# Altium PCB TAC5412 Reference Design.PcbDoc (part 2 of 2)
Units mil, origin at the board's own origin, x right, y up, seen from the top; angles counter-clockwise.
Board outline 3000 x 3000 mil, 6 copper layers (Top Layer, GND 1, Signal, GND 2, PWR, Bottom Layer), stack 60.4 mil thick; 137 components, 64 nets, 376 pads, 151 vias.
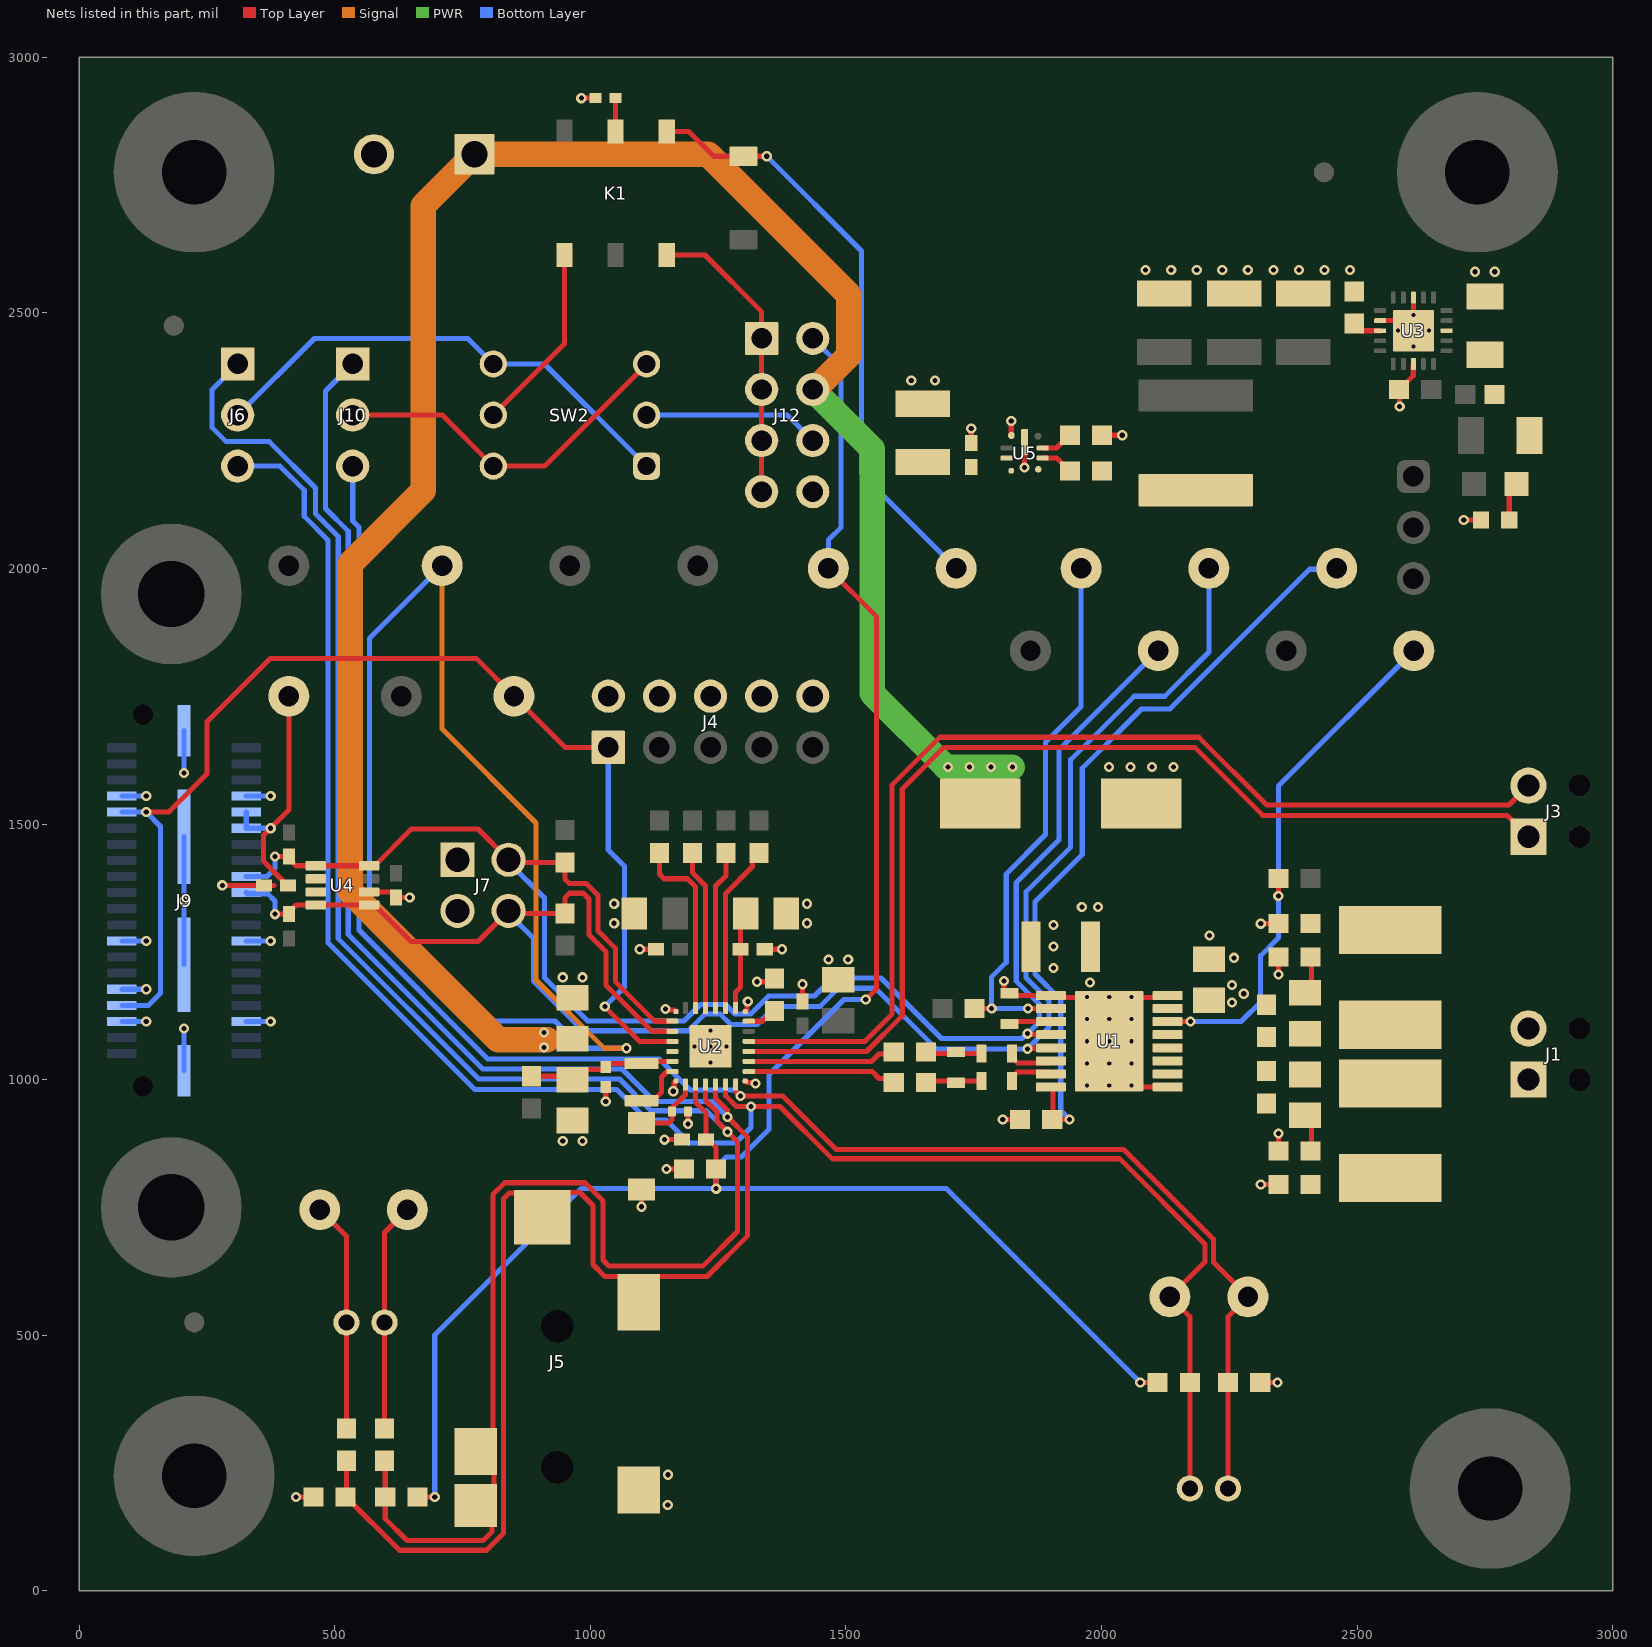
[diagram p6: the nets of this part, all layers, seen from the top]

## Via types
v1: diameter 20, hole 10, Top Layer to Bottom Layer, tented both sides, 127 vias
v2: diameter 19.68, hole 7.87, Top Layer to Bottom Layer, 19 vias
v3: diameter 19.68, hole 7.87, Top Layer to Bottom Layer, tented both sides, 5 vias

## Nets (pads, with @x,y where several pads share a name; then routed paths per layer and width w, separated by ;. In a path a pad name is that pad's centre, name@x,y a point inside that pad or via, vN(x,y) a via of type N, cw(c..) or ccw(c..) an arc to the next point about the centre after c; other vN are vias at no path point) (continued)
GND: C1.2 C2.1 C3.2 C4.2 C5.2 C11.1 C12.1 C13.2 C14.2 C15.2 C16.2 C17.2 C18.2 C19.2 C20.2 C21.2 C22.2 C23.1 C24.1 C25.2 C26.2 C27.2 C31.2 C32.2 C33.1 C34.1 C36.2 C37.2 C38.2 C39.2 C40.2 C41.2 J2.2 J4.2 J4.4 J4.6 J4.8 J4.10 J5.1 J7.1 J7.3 J9.7 J9.8 J9.25 J9.26 J9.31 J9.35 J9.36 J9.41 J9.42 J9.43 J9.44 J12.8 R5.1 R13.2 R17.2 R21.2 R22.1 R26.1 U1.1 U1.9 U1.16 U1.17 U2.25 U2.A1 U2.A2 U2.A3 U2.A4 U3.8 U3.12 U3.18 U3.21 U4.6 U5.1 U5.9 | length 2548.7
  Top Layer w10: v1(280,1380) 381.38,1380 ; v1(424.22,183.62) R13.2@458.1,183.62 ; U4.6@567.25,1367.21 609.17,1367.21 609.25,1367.13 613.19,1367.13 620,1360.32 C34.1@620,1356.38 v1(646.38,1356.38) ; v1(982.22,2919.9) R26.1@1009.99,2919.9 ; v1(1030,957.32) C17.2@1030,985.32 C17.2@1030,991.2 ; v1(1096.47,1255) C20.2@1130.35,1255 ; v1(1100,751.16) C23.1@1100,785.04 ; v1(1145,882.5) C25.2@1178.88,882.5 ; v1(1147.09,1137.91) 1149,1136 1164,1136 U2.A2@1167.09,1132.91 ; v1(1149.11,825) C26.2@1182.99,825 ; v1(1162.09,977.09) 1164,979 1164,994 U2.A3@1167.09,997.09 ; v1(1190.75,913.46) C24.1@1190.75,937.5 ; U2.A4@1302.91,997.09 1306,994 1321,994 v1(1322.91,992.09) ; U2.A1@1302.91,1132.91 1306,1136 1306,1151 v1(1307.91,1152.91) ; v1(1326.12,1191.5) C27.2@1360,1191.5 ; C22.2@1341.12,1255 v1(1375,1255) ; C14.2@1415,1152.62 v1(1415,1186.5) ; C37.2@1745,2245.52 v1(1745,2273.69) ; v1(1806.63,922) R5.1@1840.51,922 ; v1(1809.02,1192.8) 1809.02,1173.98 1814.02,1168.98 C15.2@1820,1168.98 1824.41,1164.57 U1.1@1900.83,1164.57 1904.69,1160.71 1971.54,1160.71 1971.69,1160.55 v2(1971.69,1118.31) ; U5.1@1823.33,2260.03 v1(1823.33,2288.21) ; v1(1849.37,2197.33) U5.9@1849.37,2225.51 ; U1.17@1975.78,1122.39 U1.17@2015,1083.17 ; C41.2@2000.87,2260.51 v1(2040.4,2260.51) ; v2(2015,988.39) 2017.95,985.43 U1.9@2129.17,985.43 ; v2(2015,1075) U1.17@2015,1083.17 ; U1.17@2054.22,1122.39 U1.17@2015,1083.17 ; v2(2058.31,1118.31) 2058.31,1160.71 2125.32,1160.71 U1.16@2129.17,1164.57 ; R17.2@2310.39,407.5 v1(2344.27,407.5) ; v1(2311.28,795) C12.1@2345.78,795 ; v1(2311.28,1305) C4.2@2345.78,1305 ; C11.1@2346.27,860.02 v1(2346.27,894.52) ; v1(2346.27,1205.5) C5.2@2346.27,1240 ; U3.12@2545.04,2484.69 2590.32,2484.69 2605.08,2469.92 2610,2474.84 v2(2610,2495.51) U3.8@2610,2529.96 ; v1(2583.08,2316.89) 2583.08,2348.99 C31.2@2582.01,2350.07 2582.99,2350.07 2609.72,2376.8 2609.72,2399.76 U3.18@2610,2400.04 ; v1(2708.44,2094.64) 2742.08,2094.64 R21.2@2742.44,2095
  Bottom Layer w10: J9.35@83.35,1113.78 v1(131.14,1113.78) ; J9.31@83.35,1176.77 v1(131.14,1176.77) ; J9.25@83.35,1271.26 v1(131.14,1271.26) ; J9.7@83.35,1554.72 v1(131.14,1554.72) ; J9.44@205,1017.52 v1(205,1100.1) ; J9.43@205,1225 v1(205,1349.9) J9.42@205,1475 ; v1(205,1599.9) J9.41@205,1682.48 ; J9.36@326.65,1113.78 v1(374.45,1113.78) ; J9.26@326.65,1271.26 v1(374.45,1271.26) ; J9.8@326.65,1554.72 v1(374.45,1554.72)
  other v1: 1151.34,167.94 1151.59,227.06 945.98,879.94 984.26,879.94 1977.09,1190 945.98,1200.06 984.26,1200.06 1465.98,1235.06 1504.26,1235.06 2259.04,1238.19 2211.03,1282.02 1046.44,1305.74 1423.56,1305.74 1961.34,1337.89 1992.83,1337.89 1046.44,1344.02 1423.56,1344.02 2014.44,1611.32 2056.47,1611.32 2098.49,1611.32 2140.52,1611.32 1627.63,2367.61 1674.28,2367.61 2730.74,2580.26 2769.02,2580.26 2086.11,2583.52 2136.11,2583.52 2186.11,2583.52 2236.11,2583.52 2286.11,2583.52 2336.11,2583.52 2386.11,2583.52 2436.11,2583.52 2486.11,2583.52
  other v2: 1971.69,988.39 2058.31,988.39 1971.69,1031.69 2015,1031.69 2058.31,1031.69 1971.69,1075 2058.31,1075 2015,1118.31 1971.69,1161.61 2015,1161.61 2058.31,1161.61 2610,2434.49 2579.49,2465 2640.51,2465
  other v3: 1235,1033.5 1203.5,1065 1235,1065 1266.5,1065 1235,1096.5
IN1M_D: J5.3 J5.5 J10.1 R13.1 R16.2 U2.16 | length 4192
  Top Layer w10: R13.1@522.07,183.62 626.41,79.28 796.81,79.28 830.2,112.68 830.2,767.13 841.36,778.28 858.22,778.28 J5.5@906,730.5 954.5,779 979.87,779 1005,753.87 1005,638.26 1028.26,615 1058,615 J5.3@1094.5,578.5 ; R13.1@522.6,185.13 R16.2@522.6,254.44 ; J5.3@1094.5,564.5 J5.3@1094.5,578.5 ; U2.16@1244.84,990.2 1244.84,963.39 1268.29,939.94 v1(1268.29,926.67) 1307.6,887.36 1307.6,694.35 1228.24,615 1131,615 J5.3@1094.5,578.5
  Bottom Layer w10: J10.1@535,2400 481.88,2346.89 481.88,2117.18 526.21,2072.85 526.21,1283.77 789.47,1020.51 1061.82,1020.51 1125.24,957.09 1237.87,957.09 v1(1268.29,926.67)
IN1P_D: J5.2 J5.4 J6.1 R12.1 R15.2 U2.15 | length 4244.4
  Top Layer w10: R15.2@597.4,254.44 598.69,253.16 R12.1@598.69,183.55 598.69,140.86 641.36,98.19 790.25,98.19 807.42,115.36 807.42,134.58 J5.4@775.5,166.5 811.66,202.66 811.66,236.34 J5.2@775.5,272.5 809.56,306.56 809.56,775.54 832.28,798.27 989.5,798.27 1024.69,763.07 1024.69,646.91 1036.61,635 1219.96,635 1287.6,702.64 1287.6,878.48 v1(1268.29,897.79) 1248,918.07 1248,936.5 1225.16,959.34 U2.15@1225.16,990.2
  Bottom Layer w10: J6.1@310,2400 260,2350 260,2275.33 287.43,2247.9 371.72,2247.9 462.1,2157.52 462.1,2107.04 506.69,2062.45 506.69,1275.68 781.43,1000.94 1056.73,1000.94 1118.62,939.04 1227.04,939.04 v1(1268.29,897.79)
IN2M_D: J10.3 MIC2M.1 MK2.2 R17.1 U2.18 | length 3392.8
  Top Layer w10: U2.18@1284.21,990.2 1284.21,977.27 v1(1293.59,967.89) 1376.11,967.89 1480.38,863.62 2042.94,863.62 2218.72,687.84 2218.72,642.66 MIC2M.1@2286.38,575 2247.4,536.02 R17.1@2247.4,407.5 MK2.2@2247.4,200
  Bottom Layer w10: J10.3@535,2200 535,2092.62 547.12,2080.5 547.12,1292.42 799.02,1040.51 1134.78,1040.51 1195.45,979.84 1281.64,979.84 v1(1293.59,967.89)
IN2P_D: J6.3 MIC2P.1 MK2.1 R14.2 U2.17 | length 3699.9
  Top Layer w10: U2.17@1264.53,983.39 U2.17@1264.53,990.2 ; U2.17@1264.61,983.39 1264.61,968.19 1285.33,947.46 v1(1314.02,947.46) 1370.96,947.46 1473.23,845.19 2035.31,845.19 2201.93,678.57 2201.93,643.31 MIC2P.1@2133.62,575 2172.6,536.02 R14.2@2172.6,407.5 MK2.1@2172.6,200
  Bottom Layer w10: J6.3@310,2200 392.97,2200 440.15,2152.82 440.15,2101.89 486.91,2055.13 486.91,1267.49 773.74,980.66 1051.37,980.66 1111.16,920.87 1148.13,920.87 1193.08,875.92 1283.87,875.92 1314.02,906.07 v1(1314.02,947.46)
INM-A: J10.2 SW2.3 SW2.6 | length 674.3
  Top Layer w10: J10.2@560,2300 710,2300 SW2.6@810,2200 910,2200 SW2.3@1110,2400
INP-A: J6.2 SW2.1 SW2.4 | length 965.7
  Bottom Layer w10: J6.2@310,2300 460,2450 760,2450 SW2.4@810,2400 910,2400 SW2.1@1110,2200
IOVDD-MB: C33.2 IOVDD-MB1.1 J9.10 J9.12 U4.2 U4.3 | length 492
  Top Layer w10: C33.2@408.62,1380 404.68,1380 397.87,1386.81 397.87,1389.72 360.55,1427.04 360.55,1477.83 410,1527.28 IOVDD-MB1.1@410,1750
  Bottom Layer w10: J9.10@326.65,1523.23 J9.12@326.65,1491.73 v1(374.45,1491.73)
IRQ/IRQZ: J4.1 J9.9 J9.33 MCLK.1 U2.9 | length 2355.7
  Top Layer w10: v1(131.14,1523.23) 175.11,1523.23 250,1598.12 250,1660 250.11,1660.11 250.11,1699.92 374.22,1824.03 776.47,1824.03 MCLK.1@850.5,1750 950.5,1650 J4.1@1035,1650 ; v1(1028.26,1142.8) 1028.26,1142.55 1095.96,1074.84 U2.9@1160.2,1074.84
  Bottom Layer w10: J9.33@83.35,1145.28 135.39,1145.28 159.13,1169.02 159.13,1495.24 v1(131.14,1523.23) J9.9@83.35,1523.23 ; v1(1028.26,1142.8) 1066.53,1181.07 1066.53,1417.51 1035,1449.04 J4.1@1035,1650
MICBIAS: C25.1 C26.1 J12.2 MICBIAS1.1 R12.2 R14.1 U2.14 | length 4171
  Top Layer w10: R12.2@661.68,183.55 v1(695.56,183.55) ; U2.14@1205.47,990.2 1205.47,955.68 1226.12,935.03 C25.1@1226.12,882.5 1230.06,882.5 1245.98,866.58 C26.1@1245.98,825 v1(1245.98,786.61) ; MICBIAS1.1@1465.5,2000 1560,1905.5 1560,1177.8 v1(1538.69,1156.5) ; v1(2075.73,407.5) R14.1@2109.61,407.5
  Bottom Layer w10: v1(695.56,183.55) 695.56,500.56 981.61,786.61 v1(1245.98,786.61) ; J12.2@1435,2450 1490.5,2394.5 1490.5,2080.5 1465.5,2055.5 MICBIAS1.1@1465.5,2000 ; v1(1538.69,1156.5) 1496.12,1156.5 1349.49,1009.87 1349.49,902.96 1295.37,848.84 1266.39,848.84 1245.98,828.42 v1(1245.98,786.61) ; v1(2075.73,407.5) 1696.62,786.61 v1(1245.98,786.61)
NetC4_1: C4.1 J1.2 L1.2
NetC5_1: C5.1 R1.1 | length 78.8
  Top Layer w10: R1.1@2397.75,1170 2410.55,1182.8 C5.1@2410.55,1243.5
NetC6_1: C6.1 U1.6 | length 89.4
  Top Layer w10: C6.1@1825,1051 1825,1043.5 1835.74,1032.76 1896.97,1032.76 U1.6@1900.83,1036.61
NetC6_2: C6.2 C10.2 R6.2 | length 119.7
  Top Layer w10: R6.2@1646.5,1054 1649.5,1051 C6.2@1765,1051
NetC7_1: C7.1 L1.1 R1.2 U1.12
NetC7_2: C7.2 U1.13
NetC8_1: C8.1 U1.7 | length 89.4
  Top Layer w10: C8.1@1825,996.64 1825,1004.14 1835.74,1014.88 1896.97,1014.88 U1.7@1900.83,1011.02
NetC8_2: C8.2 C10.1 R7.2 | length 119.7
  Top Layer w10: R7.2@1646.5,994 1649.5,997 C8.2@1765,997
NetC9_1: C9.1 L2.1 R4.1 U1.11
NetC9_2: C9.2 U1.10
NetC11_2: C11.2 R4.2 | length 78.8
  Top Layer w10: R4.2@2397.75,930 2410.55,917.2 C11.2@2410.55,856.5
NetC12_2: C12.2 J1.1 L2.2
NetC15_1: C15.1 U1.3 | length 82.7
  Top Layer w10: C15.1@1820,1108.98 1824.41,1113.39 U1.3@1900.83,1113.39
NetC17_1: C17.1 C18.1 L3.1 L4.1 U2.11 | length 293.7
  Top Layer w10: L3.1@885,1006.5 958.5,1006.5 C18.1@965,1000 985,1020 1025.32,1020 C17.1@1030,1024.69 1030,1026.58 1034.84,1031.42 L4.1@1100,1031.42 1103.98,1035.39 1160.12,1035.39 U2.11@1160.2,1035.47
NetC21_1: C21.1 C22.1 U2.1 | length 193.2
  Top Layer w10: U2.1@1284.21,1139.8 1284.21,1171.48 1293.88,1181.14 1293.88,1315.38 C21.1@1303.5,1325
NetC23_2: C23.2 C24.2 U2.13 | length 142
  Top Layer w10: C23.2@1100,914.96 1153.39,914.96 1159.25,920.82 C24.2@1159.25,937.5 1162.13,940.37 1162.13,947.1 1185.79,970.76 U2.13@1185.79,990.2
NetC27_1: C27.1 U2.24 | length 60.8
  Top Layer w10: U2.24@1309.8,1114.21 1336.69,1114.21 1360,1137.52 C27.1@1360,1138.5
NetC30_1: C30.1 R20.1 R22.2 U3.3
NetC32_1: C32.1 U3.13 | length 56.7
  Top Layer w10: C32.1@2494.37,2479.02 2494.37,2478.7 2508.07,2465 U3.13@2545.04,2465
NetC35_1: C35.1 U5.6 | length 64.1
  Top Layer w10: U5.6@1884.8,2215.67 1912.72,2215.67 1923.19,2205.2 1923.19,2204.21 1936.89,2190.51 C35.1@1937.87,2190.51
NetC35_2: C35.2 L5.1 U5.5
NetC41_1: C41.1 U5.7 | length 63.5
  Top Layer w10: U5.7@1884.8,2235.35 1911.73,2235.35 1936.89,2260.51 C41.1@1937.87,2260.51
NetD1_2: D1.2 R21.1 | length 75.7
  Top Layer w10: R21.1@2797.56,2095 2797.56,2151.22 D1.2@2811.34,2165
NetDIAGSW1_1: DIAGSW1.1 K1.1 SW1.2 | length 1175.6
  Top Layer w10: K1.1@1149.36,2854.98 1191.92,2854.98 1240.63,2806.28 SW1.2@1299.36,2806.28 v1(1345,2806.28)
  Bottom Layer w10: v1(1345,2806.28) 1530.15,2621.12 1530.15,2185.35 DIAGSW1.1@1715.5,2000
NetFAULT_1: FAULT.1 R2.2 U1.14 | length 1044
  Top Layer w10: U1.14@2129.17,1113.39 v1(2174,1113.39) ; v1(2345.78,1359.18) R2.2@2345.78,1393.68
  Bottom Layer w10: v1(2174,1113.39) 2272.65,1113.39 2311.24,1151.97 2311.24,1242.33 2345.78,1276.88 v1(2345.78,1359.18) 2345.78,1574.23 FAULT.1@2610.9,1839.35
NetJ3_1: J3.1 U2.21 | length 2104
  Top Layer w10: U2.21@1309.8,1055.16 1540.28,1055.16 1609.94,1124.82 1609.94,1568.46 1691.48,1650 2182.11,1650 2315.11,1517 2793,1517 J3.1@2835,1475
NetJ3_2: J3.2 U2.22 | length 2105
  Top Layer w10: U2.22@1309.8,1074.84 1536.92,1074.84 1590.26,1128.18 1590.26,1576.61 1683.33,1669.69 2190.26,1669.69 2322.95,1537 2797,1537 J3.2@2835,1575
NetJ12_1: J12.1 J12.3 J12.5 J12.7 K1.6 | length 583.5
  Top Layer w10: K1.6@1149.36,2612.86 1224.02,2612.86 1335,2501.87 J12.7@1335,2150
NetJ12_6: J12.6 SW2.2 | length 345.7
  Bottom Layer w10: SW2.2@1110,2300 1385,2300 J12.6@1435,2250
NetK1_2: K1.2 R26.2 | length 64.9
  Top Layer w10: K1.2@1049.36,2854.98 R26.2@1049.36,2919.9
NetK1_4: K1.4 SW2.5 | length 370.6
  Top Layer w10: SW2.5@810,2300 949.36,2439.36 K1.4@949.36,2612.86
NetL4_2: L4.2 U2.12 | length 101.3
  Top Layer w10: L4.2@1100,958.58 1122.64,958.58 1139.11,975.05 1139.11,1004.85 1150.05,1015.79 U2.12@1160.2,1015.79
NetMIC1M_1: MIC1M.1 MK1.2 R16.1 | length 449.5
  Top Layer w10: MIC1M.1@470.61,745.48 522.6,693.49 MK1.2@522.6,525 R16.1@522.6,317.5
NetMIC1P_1: MIC1P.1 MK1.1 R15.1 | length 446.5
  Top Layer w10: R15.1@597.4,317.43 MK1.1@597.4,525 597.4,700.88 MIC1P.1@641.99,745.48
NetMUTE_1: MUTE.1 R5.2 U1.8 | length 1512.5
  Top Layer w10: U1.8@1900.83,985.43 1901.14,985.43 1905,981.58 R5.2@1905,922 ; R5.2@1903.5,922 R5.2@1905,922 ; v1(1937.38,922) R5.2@1905,922
  Bottom Layer w10: v1(1937.38,922) 1920.05,939.34 1920.05,1156.4 1869.67,1206.77 1869.67,1348.12 1962.13,1440.57 1962.13,1609.12 2078.01,1725 2133.56,1725 2406.83,1998.27 2449.11,1998.27 2450.84,2000 MUTE.1@2460,2000
NetR3_2: R3.2 STANDBY.1 U1.2 | length 1082.8
  Top Layer w10: R3.2@1751.5,1138.98 v1(1785,1138.98) ; v1(1856,1138.98) U1.2@1900.83,1138.98
  Bottom Layer w10: v1(1856,1138.98) v1(1785,1138.98) 1785,1200.97 1813.42,1229.39 1813.42,1402.32 1890.35,1479.26 1890.35,1660.06 1960,1729.72 STANDBY.1@1960,2000
NetR6_1: R6.1 U2.20 | length 281.4
  Top Layer w10: U2.20@1309.8,1035.47 1549.85,1035.47 1564.68,1050.3 1579.8,1050.3 R6.1@1583.5,1054
NetR7_1: R7.1 U2.19 | length 284.9
  Top Layer w10: U2.19@1309.8,1015.79 1551.24,1015.79 1564.68,1002.35 1578.82,1002.35 1583.5,997.67 R7.1@1583.5,994
NetR8_1: R8.1 U2.2 | length 330.8
  Top Layer w10: U2.2@1264.53,1139.8 1264.53,1363.98 1317.23,1416.68 1317.23,1430.73 R8.1@1330,1443.5
NetR9_1: R9.1 U2.5 | length 361.8
  Top Layer w10: R9.1@1135,1443.5 1135,1401.98 1144.19,1392.8 1189.7,1392.8 1205.47,1377.02 U2.5@1205.47,1139.8 ; R9.1@1135,1446.69 R9.1@1136.59,1445.1
NetR10_1: R10.1 U2.4 | length 314.1
  Top Layer w10: R10.1@1200,1443.5 1200,1403.99 1225.16,1378.84 U2.4@1225.16,1139.8
NetR11_1: R11.1 U2.3 | length 312.1
  Top Layer w10: U2.3@1244.84,1139.8 1244.84,1378.48 1265,1398.64 R11.1@1265,1443.5
SCL: J7.2 J9.18 R18.2 R23.1 SCL1.1 U1.4 U2.7 U4.1 U4.8 | length 3407.7
  Top Layer w10: v1(383.19,1436.38) R23.1@410,1436.38 410,1432.44 424.06,1418.39 U4.1@462.75,1418.39 U4.8@567.25,1418.39 578,1418.39 649.65,1490.04 779.96,1490.04 J7.2@840,1430 ; J7.2@865,1425 R18.2@950,1425 950,1392.39 958.5,1383.88 991.59,1383.88 1015.11,1360.35 1015.11,1290.64 1048.75,1257 1048.75,1191.56 1126.1,1114.21 U2.7@1160.2,1114.21 ; v1(1855,1089.8) 1856,1088.8 1899.83,1088.8 U1.4@1900.83,1087.8
  Bottom Layer w10: J9.18@326.65,1397.24 326.94,1397.53 367.14,1397.53 383.19,1413.58 v1(383.19,1436.38) ; J7.2@840,1425 910,1355 910,1199.29 994.9,1114.39 1183.18,1114.39 1215.58,1146.79 1264.2,1146.79 1283,1127.99 1313.31,1127.99 1348.81,1163.49 1438.49,1163.49 1473.99,1198.99 1568.27,1198.99 1686.97,1080.29 1844.14,1080.29 1853.65,1089.8 v1(1855,1089.8) 1878.38,1113.17 1878.38,1147.32 1833.14,1192.55 1833.14,1385.43 1916.83,1469.12 1916.83,1645.28 SCL1.1@2110.9,1839.35
SDA: J7.4 J9.20 R19.2 R24.1 SDA1.1 U1.5 U2.8 U4.4 U4.5 | length 3595.7
  Top Layer w10: v1(383.19,1323.62) R24.1@410,1323.62 410,1327.56 424.06,1341.62 U4.4@462.75,1341.62 U4.5@567.25,1341.62 578,1341.62 649.65,1269.96 779.96,1269.96 J7.4@840,1330 ; J7.4@865,1325 R19.2@950,1325 950,1355.18 959.28,1364.46 986.23,1364.46 997.24,1353.46 997.24,1283.23 1030.88,1249.6 1030.88,1184.16 1120.51,1094.53 U2.8@1160.2,1094.53 ; v1(1855,1060.21) 1856,1061.21 1899.83,1061.21 U1.5@1900.83,1062.21
  Bottom Layer w10: J9.20@326.65,1365.75 328.76,1363.65 368.86,1363.65 383.19,1349.32 v1(383.19,1323.62) ; J7.4@840,1325 888.46,1276.54 888.46,1192.8 985.62,1095.64 1191.43,1095.64 1223.78,1127.99 1254.22,1127.99 1274.42,1107.79 1326.42,1107.79 1361.9,1143.27 1449.58,1143.27 1485.06,1178.75 1557.86,1178.75 1676.4,1060.21 v1(1855,1060.21) 1897.46,1102.66 1897.46,1153.97 1852.46,1198.96 1852.46,1367.45 1939.45,1454.44 1939.45,1625.6 2063.85,1750 2123.49,1750 2210,1836.51 SDA1.1@2210,2000
VBATIN: C1.1 C2.2 C3.1 C16.1 C36.1 C37.1 J2.1 J12.4 U1.15 U2.10 U5.3 U5.4 VBAT.1 | length 6572.8
  PWR w50: J12.4@1435,2350 1551.12,2233.88 1551.12,1755.6 1695.4,1611.32 v1(1699.48,1611.32) v1(1741.51,1611.32) v1(1783.53,1611.32) v1(1825.56,1611.32)
  Signal w10: VBAT.1@710,2005.5 710,1685.93 893.8,1502.13 893.8,1194.62 1027,1061.42 v1(1070.75,1061.42)
  Signal w50: 915.22,1078.09 819.59,1078.09 530.31,1367.37 530.31,2009.28 672.74,2151.71 672.74,2709.48 J2.1@773.43,2810.16 1230.52,2810.16 1505.5,2535.18 1505.5,2416.45 1439.05,2350 J12.4@1435,2350
  Bottom Layer w10: VBAT.1@710,2005.5 567.48,1862.98 567.48,1301.02 754.08,1114.42 930.58,1114.42 983.58,1061.42 v1(1070.75,1061.42)
  other v1: 909.19,1063.15 909.19,1092.09 2255,1150.91 2278.16,1167.96 2255,1185 1905.92,1218.23 1905.92,1260.25 1905.92,1302.28
pads on no net: FID1.1 FID2.1 FID3.1 FID4.1 FID5.1 FID6.1 H1.1 H2.1 H3.1 H4.1 H5.0 H6.0 H7.0 H8.0 H9.0 H10.0 H11.0 H12.0 J1.MH1 J1.MH2 J3.MH1 J3.MH2 J5.MH1 J5.MH2 J9.1 J9.2 J9.3 J9.4 J9.5 J9.6 J9.11 J9.13 J9.14 J9.15 J9.16 J9.17 J9.19 J9.21 J9.22 J9.23 J9.24 J9.28 J9.29 J9.30 J9.38 J9.40 J9.45 J9.46 K1.3 K1.5 U3.2 U3.4 U3.5 U3.6 U3.7 U3.9 U3.10 U3.11 U5.2

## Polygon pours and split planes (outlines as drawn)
GND on PWR "GND" (solid, remove dead copper, pour order 4): 3000,3000 0,3000 0,0 3000,0
"+3.3V MB" on PWR "+3.3V MB" (solid, remove dead copper, pour order 0): 588.15,1500 429.47,1500 424.42,1494.95 424.42,1041.91 760.86,705.48 2169.79,705.48 2749.38,1285.07 2749.38,1609.96 2864.9,1725.47 2864.9,1884.3 2725.59,2023.6 2584.22,2023.6 2573.11,2012.49 2573.11,1921.31 2584.24,1910 2654.26,1910 2700.9,1863.36 2700.9,1818.64 2562.91,1680.65 2562.91,1352.3 2108.4,897.79 853.33,897.79 672.15,1078.97 672.15,1416
+3.3V on PWR "+3.3V Analog" (solid, remove dead copper, pour order 3): 891.42,907.98 862.04,907.98 830.5,939.53 830.5,1085.94 864.23,1119.67 1200.5,1119.67 1623.95,1543.12 1868.25,1543.12 1900.9,1575.77 1900.9,2090.57 1491.47,2500 1264.73,2500 1218.3,2546.43 1218.3,2643.57 1249.73,2675 1981.42,2675 2366.4,2290.02 2653.63,2290.02 2725.51,2218.14 2725.51,1843.25 2562.91,1680.65 2562.91,1352.3 2118.6,907.98
GND on Signal "GND" (solid, remove dead copper, pour order 12): 0,3000 0,0 3000,0 3000,3000
+3.3V on Signal "+3.3V Digital" (solid, remove dead copper, pour order 10): 1462.29,1231.25 1486.07,1255.02 1667.09,1255.02 2445.87,2033.8 2725.51,2033.8 2725.51,2218.14 2653.63,2290.02 2193.9,2290.02 1458.6,1554.72 1008.78,1554.72 961.3,1507.24 961.3,1278.79 1008.84,1231.25
GND on GND 1 "GND" (solid, remove dead copper, pour order 2): 0,3000 0,0 3000,0 3000,3000
GND on Bottom Layer "GND" (solid, remove dead copper, pour order 8): 0,3000 0,0 3000,0 3000,3000
GND on GND 2 "GND" (solid, remove dead copper, pour order 9): 0,3000 0,0 3000,0 3000,3000
GND on Top Layer "GND" (solid, remove dead copper, pour order 7): 0,3000 0,0 3000,0 3000,3000

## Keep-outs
Keep-Out Layer:
  text ".Layer_Name" at 537,-858.49 h60

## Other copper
Top Layer:
  region net NetC30_1: 2713.58,2392.32 2756.81,2349.09 2756.81,2326.3 2790.59,2292.52 2790.59,2223.58 2862.68,2223.58 2862.68,2377.24 2770.2,2469.72 2665.13,2469.72 2665.13,2460.28 2687.72,2460.28 2713.58,2434.41
  region net NetC9_2: 2121.92,1002.17 2235.7,1002.17 2304.05,933.82 2341.45,933.82 2341.45,973.19 2308.75,973.19 2262.06,1019.88 2121.92,1019.88
  region net NetC12_2: 2397.65,822.27 2432.15,822.27 2464.61,854.72 2606.65,854.72 2692.95,941.02 2692.95,994.17 2741.13,1042.35 2883.01,1042.35 2883.01,890.29 2699.04,706.32 2504.06,706.32 2459.06,706.32 2389.08,776.3 2389.08,813.7
  region net NetC9_1: 2659.68,1045.47 2665.39,1039.76 2665.39,945.28 2464.61,945.28 2443.98,965.9 2372.35,965.9 2353.25,985 2315.86,985 2273.1,1027.76 2121.92,1027.76 2121.92,1045.47
  region net NetC7_1: 2658.5,1053.35 2665.39,1060.24 2665.39,1154.72 2464.61,1154.72 2443.98,1134.1 2372.35,1134.1 2353.25,1115 2315.86,1115 2271.92,1071.06 2121.92,1071.06 2121.92,1053.35
  region net NetC7_2: 2121.92,1096.65 2234.52,1096.65 2304.05,1166.18 2341.45,1166.18 2341.45,1126.81 2312.39,1126.81 2264.52,1078.94 2121.92,1078.94
  region net VBATIN: 1683.78,1615.48 1683.78,1337.73 1814.66,1206.85 1919.08,1206.85 1919.08,1314.07 1841.26,1391.89 1841.26,1615.33 1829.56,1627.03 1695.33,1627.03
  region net NetC4_1: 2397.65,1277.73 2432.15,1277.73 2464.61,1245.28 2606.65,1245.28 2692.95,1158.98 2692.95,1105.83 2741.13,1057.65 2883.01,1057.65 2883.01,1209.71 2699.04,1393.68 2504.06,1393.68 2459.06,1393.68 2389.08,1323.7 2389.08,1286.3
  region net VBATIN: 2129.17,1130.12 2256.23,1130.12 2289.32,1163.21 2289.32,1180.61 2273.25,1196.69 2195.74,1196.69 2170,1170.94 2170,1160.28 2157.56,1147.84 2129.17,1147.84
  region net VBATIN: 1160.2,1050.24 903.58,1050.24 896.42,1057.4 896.42,1097.83 903.59,1105 1045.3,1105 1090.22,1060.08 1160.2,1060.08
  region net +3.3V: 1345.66,1099.45 1355.71,1109.5 1380.53,1109.5 1392.15,1121.13 1434.63,1121.13 1453.5,1140 1535.82,1140 1543.88,1131.94 1543.88,1098.46 1535.05,1089.63 1309.83,1089.63 1309.8,1089.61 1309.8,1099.45
  region net +3.3V: 1141,1374.76 1146.86,1380.62 1186.53,1380.62 1191.5,1375.65 1191.5,1356.5 1191.5,1130.75 1188.74,1127.99 1182.83,1127.99 1180.87,1129.96 1180.87,1152.64 1160.37,1173.13 1160.37,1267.1 1141,1286.48
  region net IOVDD-MB: 480.7,1401.8 402.86,1401.8 392.87,1391.81 392.87,1368.19 402.86,1358.21 480.7,1358.21 482.5,1360.01 482.5,1400
  region net VBATIN: 1716.16,2220.59 1671.65,2265.09 1597.61,2265.09 1462.7,2400 1420,2400 1393.92,2373.92 1393.92,2326.54 1426.19,2294.26 1454.43,2294.26 1570.43,2178.27 1828.53,2178.27 1829.68,2179.42 1829.68,2215.5 1824.59,2220.59
  region net GND: 1596.85,2296.59 1596.85,2356.29 1620.65,2380.09 1679.35,2380.09 1703.15,2356.29 1703.15,2296.64
  region net GND: 2786.42,2516.5 2786.42,2581.11 2775.33,2592.21 2724.43,2592.21 2713.58,2581.36 2713.58,2516.5
  region net GND: 2069.13,2512.01 2069.13,2594.13 2077.06,2602.06 2486.15,2602.06 2513.07,2575.14 2513.07,2522.32 2502.76,2512.01
  region net GND: 1358.5,1356.5 1429.33,1356.5 1435.51,1350.33 1435.51,1299.43 1429.58,1293.5 1358.5,1293.5
  region net GND: 1111.5,1356.5 1040.67,1356.5 1034.49,1350.33 1034.49,1299.43 1040.42,1293.5 1111.5,1293.5
  region net GND: 1053,151.5 1154.93,151.5 1164.25,160.82 1164.25,234.44 1155.19,243.5 1053,243.5
  region net GND: 933.5,945 933.5,874.17 939.67,867.99 990.57,867.99 996.5,873.92 996.5,945
  region net GND: 933.5,1135 933.5,1205.83 939.67,1212.01 990.57,1212.01 996.5,1206.08 996.5,1135
  region net GND: 1453.5,1170 1453.5,1240.83 1459.67,1247.01 1510.57,1247.01 1516.5,1241.08 1516.5,1170
  region net "+3.3V EXT": 2733.19,2363.7 2733.19,2316.73 2752.28,2297.64 2752.28,2141.38 2585.38,2141.38 2570.14,2156.62 2570.14,2272.62 2624.96,2327.44 2624.96,2409.87 2626.94,2411.85 2652.93,2411.85 2653.51,2411.27 2663.15,2420.91 2663.15,2428.37 2665.13,2430.35 2685.61,2430.35 2686.77,2429.19 2686.77,2410.12
  region net NetC35_2: 1981.18,2209.21 1981.18,2181.32 1963.17,2163.31 1907.57,2163.31 1896.61,2174.27 1896.61,2198.92 1894.65,2200.89 1871.02,2200.89 1869.05,2198.92 1869.05,2152.26 1899.82,2121.5 2294.68,2121.5 2296.57,2123.39 2296.57,2183.38 2270.74,2209.21
  region net +5.0V: 1966.69,2450.04 1867.09,2350.43 1867.09,2251.91 1896.61,2251.91 1896.61,2277.32 1925.83,2306.54 2478.58,2306.54 2552.75,2380.71 2586.36,2380.71 2595.04,2389.39 2595.04,2409.87 2593.06,2411.85 2567.89,2411.85 2556.85,2422.89 2556.85,2448.06 2554.87,2450.04
  text ".Layer_Name" at 537,-858.49 h60
PWR:
  region net GND: 1951.85,1193.05 1968.8,1210 2037.98,1210 2078.15,1169.83 2078.15,980.17 2066.53,968.54 1963.47,968.54 1951.85,980.17 1951.85,1035.64
  pour cut-out: 1362.24,1114.54 ccw(c1362.24,1099.54) 1347.24,1099.54 ccw(c1362.24,1099.54) 1362.24,1084.54 ccw(c1362.24,1099.54) 1377.24,1099.54 ccw(c1362.24,1099.54)
  pour cut-out: 2360.55,1892.08 2360.4,1892.08 ccw(c2360.4,1839.72) 2308.05,1839.72 ccw(c2360.69,1839.72) 2360.69,1787.08 2360.72,1787.08 ccw(c2360.72,1839.4) 2413.05,1839.4 2413.05,1839.58 ccw(c2360.55,1839.58)
  pour cut-out: 1180.24,1184.4 ccw(c1180.24,1169.4) 1165.25,1169.4 ccw(c1180.25,1169.4) 1180.25,1154.4 ccw(c1180.25,1169.4) 1195.25,1169.4 ccw(c1180.25,1169.4)
  pour cut-out: 984.5,1502.99 ccw(c984.5,1487.99) 969.5,1487.99 ccw(c984.5,1487.99) 984.5,1472.99 ccw(c984.5,1487.99) 999.5,1487.99 ccw(c984.5,1487.99)
  pour cut-out: 984.5,1277.01 ccw(c984.5,1262.01) 969.5,1262.01 ccw(c984.5,1262.01) 984.5,1247.01 ccw(c984.5,1262.01) 999.5,1262.01 ccw(c984.5,1262.01)
  pour cut-out: 1070.75,1076.42 ccw(c1070.75,1061.42) 1055.75,1061.42 ccw(c1070.75,1061.42) 1070.75,1046.42 ccw(c1070.75,1061.42) 1085.75,1061.42 ccw(c1070.76,1061.42)
  pour cut-out: 709.82,2058.12 709.68,2058.12 ccw(c709.68,2005.76) 657.32,2005.76 ccw(c709.97,2005.76) 709.97,1953.12 710,1953.12 ccw(c710,2005.44) 762.32,2005.44 762.32,2005.62 ccw(c709.82,2005.62)
Signal:
  pour cut-out: 2360.72,1891.96 2360.58,1891.96 ccw(c2360.58,1839.61) 2308.22,1839.61 ccw(c2360.87,1839.61) 2360.87,1786.96 2360.9,1786.96 ccw(c2360.9,1839.29) 2413.22,1839.29 2413.22,1839.46 ccw(c2360.72,1839.46)
  pour cut-out: 1180.24,1184.4 ccw(c1180.24,1169.4) 1165.25,1169.4 ccw(c1180.25,1169.4) 1180.25,1154.4 ccw(c1180.25,1169.4) 1195.25,1169.4 ccw(c1180.25,1169.4)
Bottom Layer:
  region net VBATIN: 2256.23,1130.12 2289.32,1163.21 2289.32,1180.61 2148.22,1321.72 1897.46,1321.72 1888.5,1312.77 1888.5,1215.83 1897.47,1206.87 2083.01,1206.87 2159.76,1130.12
  text ".Layer_Name" at 537,-858.49 h60

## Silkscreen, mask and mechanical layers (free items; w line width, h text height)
Top Overlay:
  circle w7: c1381.97,587.76 r4
  lines w5: 1397.82,792.94 1689.94,792.94 ; 1418.12,2522.85 1428.66,2512.32 ; 1428.66,2553.74 1428.66,2512.32 ; 1439.19,2522.85 1428.66,2512.32 ; 1456.24,578 1456.24,903 ; 1473.5,2577.34 1514.92,2577.34 ; 1504.39,2566.8 1514.92,2577.34 ; 1504.39,2587.87 1514.92,2577.34 ; 1514.67,578 1514.67,903 ; 1532.54,2503.75 1808.28,2503.75 ; 1533.52,2444.31 1808.28,2444.99 ; 1533.79,2561.9 1808.28,2562.5 ; 1573.09,578 1573.09,903 ; 1631.52,578 1631.52,903 ; 1397.82,578 1397.82,903 1689.94,903 1689.94,578 1397.82,578 ; 1532.54,2386.23 1808.28,2386.23 1808.28,2621.26 1532.54,2621.26 1532.54,2386.23
  lines w8: 1501.43,1570.09 1501.43,1587.23 ; 1518.57,1587.23 1501.43,1587.23 ; 1542.95,921.81 1542.95,1545.71 1501.43,1587.23
  text "GND" at 486.43,2624.19 h50
  text "VBATIN" at 646.49,2624.19 h50
  text "MICBIAS" at 1540.96,2576.85 h50
  text "VBAT_IN" at 1540.96,2521.42 h50
  text "INx" at 1540.96,2453.04 h50
  text "GND" at 1540.96,2399.99 h50
  text "IN1P_D" at 91.74,2373.43 h50
  text "IN1M_D" at 599.17,2372.85 h50
  text "INP-A" at 124.54,2285.88 h50
  text "INM-A" at 599.17,2284.82 h50
  text "IN2M_D" at 599.17,2179.02 h50
  text "IN2P_D" at 91.74,2177.63 h50
  text "+3.3V EXT" at 2339.01,2166.07 h50
  text "+3.3V MB" at 2663.82,1962.59 h50
  text "+3.3V" at 353.89,1910.69 h50
  text "*" at 1037.67,1815.03 h50
  text "+3.3V" at 2300.2,1744.8 h50
  text "GND" at 752.24,1514.82 h50 r90
  text "SCL" at 855.91,1514.82 h50 r90
  text "SDA" at 855.91,1165.76 h50 r90
  text "GND" at 754.29,1163.4 h50 r90
  text "*" at 1455.31,916.63 h50
  text "J4" at 1400.63,916.46 h50
  text "GND" at 1444.25,800.12 h50 r90
  text "GND" at 1501.91,800.12 h50 r90
  text "GND" at 1558.97,800.12 h50 r90
  text "GND" at 1618.97,800.12 h50 r90
  text "GND" at 1676.93,800.12 h50 r90
  text "MCLK" at 1444.29,588.76 h50 r90
  text "BCLK1" at 1500.05,588.76 h50 r90
  text "DIN1" at 1558.61,588.76 h50 r90
  text "DOUT1" at 1617.42,588.76 h50 r90
  text "FSYNC1" at 1676.36,588.76 h50 r90
  text "'.PRJ_Number' '.PCB_Rev'" at 1258.11,393.67 h80
  text ".Layer_Name" at 537,-858.49 h60
Bottom Overlay:
  text ".Layer_Name" at 537,-858.49 h60
Top Paste:
  text ".Layer_Name" at 537,-858.49 h60
Bottom Paste:
  text ".Layer_Name" at 537,-858.49 h60
Top Solder:
  text ".Layer_Name" at 537,-858.49 h60
  text ".Layer_Name" at 537,-858.49 h60
Bottom Solder:
  text ".Layer_Name" at 537,-858.49 h60
Drill Guide:
  text ".Layer_Name" at 537,-858.49 h60
M1 Board Outline:
  the board outline again, w10
  text ".Layer_Name" at 537,-858.49 h60
M2 Board Dimensions:
  rectangle: -40,-275 85,-150
  rectangle: 85,-400 460,-275
  lines w7: -40,-275 960,-275 ; 85,-400 85,-150 ; 210,-400 210,-150 ; 460,-400 460,-150 ; 710,-400 710,-150 ; -40,-400 960,-400 960,-150 -40,-150 -40,-400
  text ".Layer_Name" at 537,-858.49 h60
M3 3D STEP Top:
  text ".Layer_Name" at 537,-858.49 h60
M4 3D STEP Bottom:
  text ".Layer_Name" at 537,-858.49 h60
M5 Assembly Top:
  lines w10: -332,-930.17 6268,-930.17 ; -332,-726.83 6270,-726.83 ; -332,-523.5 -332,-1133.5 3673,-1133.5 6270,-1133.5 6270,-523.5 -331.5,-523.5 -331.5,-1133.5 1244,-1133.5 ; 2133,-1133.5 2133,-523.5 ; 3400,-726.83 3400,-523.5 ; 4240,-726.83 4240,-523.5 ; 4862,-1140 4862,-937.17
  text "COMPONENTS MARKED 'DNP' SHOULD NOT BE POPULATED." at 1113.5,-318.5 h60
  text "ASSEMBLY VARIANT:" at 1113,-434 h60
  text ".VariantName" at 2149,-434 h60
  text "PCB VIEWED FROM TOP SIDE" at -268.5,-655.67 h60
  text "BOARD #:" at 2208,-655.67 h60
  text ".PRJ_Number" at 2753.5,-655.67 h60
  text "REV:" at 3598,-655.67 h60
  text ".PCB_Rev" at 3889.5,-655.67 h60
  text "SVN REV:" at 4436,-655.67 h60
  text ".VersionControl_RevNumber" at 4942,-655.67 h60
  text "TID #:" at 2208,-859 h60
  text ".TID" at 2753.5,-859 h60
  text "PLOT NAME =" at -268.5,-1064.34 h60
  text ".plot_File_Name" at 537,-1064.34 h60
  text "GENERATED    :" at 2210,-1064.34 h60
  text ".Print_Date" at 3079.5,-1064.34 h60
  text ".Print_Time" at 3808.5,-1064.34 h60
  text "TEXAS INSTRUMENTS" at 5073,-1064.34 h60
M6 Assembly Bottom:
  lines w10: -332.5,-727.33 6269.5,-727.33 ; -330.5,-930.67 6269.5,-930.67 ; 1075.5,-1140.5 1075.5,-937.67 ; 1697.5,-727.33 1697.5,-524 ; 2537.5,-727.33 2537.5,-524 ; 3804.5,-1134 3804.5,-524 ; 4693.5,-1134 6269,-1134 6269,-524 -332.5,-524 -332.5,-1134 2264.5,-1134 6269.5,-1134 6269.5,-524
  text "COMPONENTS MARKED 'DNP' SHOULD NOT BE POPULATED." at 6062,-318 h60
  text ".VariantName" at 5018,-434 h60
  text "ASSEMBLY VARIANT:" at 6057,-434 h60
  text ".VersionControl_RevNumber" at 995.5,-656.17 h60
  text "SVN REV:" at 1501.5,-656.17 h60
  text ".PCB_Rev" at 2048,-656.17 h60
  text "REV:" at 2339.5,-656.17 h60
  text ".PRJ_Number" at 3184,-656.17 h60
  text "BOARD #:" at 3729.5,-656.17 h60
  text "PCB VIEWED FROM BOTTOM SIDE" at 6206,-656.17 h60
  text ".TID" at 3184,-859.5 h60
  text "TID #:" at 3729.5,-859.5 h60
  text "TEXAS INSTRUMENTS" at 864.5,-1064.84 h60
  text ".Print_Time" at 2129,-1064.84 h60
  text ".Print_Date" at 2858,-1064.84 h60
  text "GENERATED    :" at 3727.5,-1064.84 h60
  text ".plot_File_Name" at 5400.5,-1064.84 h60
  text "PLOT NAME =" at 6206,-1064.84 h60
M9 Title Sheet:
  drawing of 57 lines, arcs and shapes, not listed
  text "1" at 699.84,8036.5 h70
  text "2" at 3195.5,8036.5 h70
  text "3" at 5684.84,8036.5 h70
  text "4" at 8191.51,8036.5 h70
  text "5" at 10690.5,8036.5 h70
  text "6" at 13195.5,8036.5 h70
  text "A" at -456.5,6893.5 h70
  text "A" at 14343.5,6893.5 h70
  text "B" at -456.5,4513.5 h70
  text "B" at 14343.5,4513.5 h70
  text "C" at -456.5,2138.5 h70
  text "C" at 14343.5,2138.5 h70
  text "PROJECT TITLE:" at 11303.5,277.5 h45
  text ".PRJ_Title" at 11353.5,144.17 h70
  text "DESIGNED FOR:" at 11303.5,-23.5 h45
  text ".PRJ_Customer" at 11353.5,-163.5 h70
  text "D" at -456.5,-231.5 h70
  text "D" at 14343.5,-231.5 h70
  text "FILE NAME:" at 11303.5,-323.5 h45
  text ".PCB_File_Name_No_Path" at 11353.5,-443.5 h70
  text "Texas Instruments (TI) and/or its licensors do not warrant the accuracy or completeness of this specification" at 6334,-605.34 h45
  text "ENGINEER:" at 11303.5,-613.5 h45
  text "LAYOUT BY:" at 12808.5,-613.5 h45
  text "or any information contained therein. TI and/or its licensors do not warrant that this design will meet" at 6289.01,-718 h45
  text ".PRJ_Engineer" at 11353.5,-768.49 h70
  text ".PCB_Layout" at 12859,-768.49 h70
  text "the specifications, will be suitable for your application or fit for any particular purpose, or will operate in" at 6289.01,-830.67 h45
  text ".Layer_Name" at 537,-858.49 h60
  text "ALTIUM DESIGNER VERSION:" at 12808.5,-923.5 h45
  text "an implementation. TI and/or its licensors do not warrant that the design is production worthy. You should" at 6289.01,-943.33 h45
  text "completely validate and test your design implementation to confirm the system functionality for your application." at 6334,-1056 h45
  text ".print_Scale" at 11353.5,-1056.83 h70
  text ".Application_BuildNumber" at 12859,-1056.83 h70
  text "1" at 699.84,-1263.5 h70
  text "2" at 3195.5,-1263.5 h70
  text "3" at 5684.84,-1263.5 h70
  text "4" at 8191.51,-1263.5 h70
  text "5" at 10690.5,-1263.5 h70
  text "6" at 13195.5,-1263.5 h70
M10 Fab Notes:
  drawing of 189 lines, arcs and shapes, not listed
  text "DESIGN INFORMATION" at 12342.02,6356.17 h60
  text "MIN. TRACK WIDTH:" at 11697.46,6224.05 h60
  text "10" at 12793.7,6224.05 h60
  text "MIL" at 12948.46,6224.05 h60
  text "5" at 12795,6115 h60
  text "MIN. CLEARANCE:" at 11697.46,6099.92 h60
  text "MIL" at 12948.46,6099.92 h60
  text "MIN. VIA PAD SIZE:" at 11697.46,5975.8 h60
  text "20" at 12763.71,5975.8 h60
  text "MIL" at 12948.46,5975.8 h60
  text "0.127mm (5MIL)" at 12392.46,5845.9 h60
  text "MINIMUM ANNULAR RING" at 11368.23,5837.67 h60
  text "EXTERNAL" at 13100.46,5837.67 h60
  text "PER" at 11568.23,5727.55 h60
  text "IPC-D-275 CLASS 2 LEVEL C" at 11788.23,5727.54 h60
  text "MIL, HOLES" at 13276.46,5627.07 h60
  text "+/-" at 12884,5618.48 h60
  text "+/-" at 13738,5618.48 h60
  text "REGISTRATION TOLERANCES:" at 11368.23,5617.42 h60
  text "METAL" at 12568,5617.42 h60
  text "5" at 13144.2,5617.42 h60
  text "3" at 13977.2,5617.42 h60
  text "MIL" at 14093.46,5617.42 h60
  text "HOLE SIZE TOLERANCE (UNLESS OTHERWISE SPECIFIED):" at 11368.23,5519.1 h60
  text "+/-" at 13738,5516.23 h60
  text "3" at 13977.2,5515.17 h60
  text "MIL" at 14093.46,5515.17 h60
  text "MATERIAL:" at 11293.46,5377.52 h60
  text "FR-4 High Tg" at 12279.9,5249 h60
  text "X" at 12135.46,5241.01 h60
  text "FR-4" at 11714.46,5236.49 h60
  text "OTHER" at 13202.46,5236.49 h60
  text "62 MIL (1.6mm) +/-10%" at 12034.56,5093.46 h60
  text "X" at 11914.46,5091.01 h60
  text "THICKNESS:" at 11368.23,5085.24 h60
  text "OTHER" at 13319.46,5085.24 h60
  text "TOLERANCE:" at 11368.23,4946.92 h60
  text "X" at 12216.46,4946.92 h60
  text "ANSI IPC-6012 TYPE 3 CLASS 2" at 12394.48,4946.92 h60
  text "OTHER +/-" at 12394.46,4802.73 h60
  text "BOW & TWIST:" at 11368.23,4657.54 h60
  text "X" at 12216.46,4657.54 h60
  text "ANSI IPC-6012 TYPE 3 CLASS 2" at 12394.48,4657.54 h60
  text "OTHER +/-" at 12394.46,4510.85 h60
  text "DRILLING:" at 11293.46,4380.23 h60
  text "NC_DRILL FILES" at 13054.46,4275.04 h60
  text "REFERENCE:" at 11368.23,4271.1 h60
  text "X" at 12025.46,4271.01 h60
  text "AS SHOWN" at 12203.46,4271.1 h60
  text "X" at 12926.46,4271.1 h60
  text "OTHER" at 13352.46,4128.85 h60
  text "PTH COPPER THICKNESS:" at 11367.91,4125.32 h60
  text "X" at 12507.14,4125.32 h60
  text "20-30 um" at 12635.14,4125.32 h60
  text "BOARD FINISH:" at 11293.46,3977.73 h60
  text "SILKSCREEN:" at 11448.68,3867.6 h60
  text "X" at 12406.46,3867.6 h60
  text "TOP" at 12523.46,3867.6 h60
  text "X" at 12916.46,3867.6 h60
  text "BOTTOM" at 13034.46,3867.6 h60
  text "SILKSCREEN COLOR:" at 11448.68,3712.41 h60
  text "X" at 12405.46,3712.41 h60
  text "WHITE" at 12523.46,3712.41 h60
  text "OTHER" at 13034.46,3712.41 h60
  text "X" at 12536.46,3568.96 h60
  text "GREEN" at 12654.46,3568.96 h60
  text "OTHER" at 13272.46,3568.96 h60
  text "SOLDER RESIST COLOR:" at 11448.68,3562.1 h60
  text "X" at 12536.46,3414.71 h60
  text "MATTE" at 12654.46,3414.71 h60
  text "SEMI-GLOSS" at 13272,3414.07 h60
  text "IMMERSION GOLD (ENIG)" at 12354.46,3241.94 h60
  text "ENEPIG" at 13692,3234.72 h60
  text "SURFACE FINISH:" at 11293.46,3233.72 h60
  text "X" at 12176.46,3233.72 h60
  text "IMM. TIN/SILVER OR EQUIV" at 11623,3096.4 h60
  text "OTHER" at 13054.46,3092.47 h60
  text "ARRAY/PANEL:" at 11293.46,2937.09 h60
  text "CUT AND TRIM PER M1 BOARD OUTLINE" at 12354.46,2928.87 h60
  text "N.C. ROUTE" at 12354.46,2792.9 h60
  text "X" at 13042.46,2792.9 h60
  text "V. SCORE" at 13220.46,2792.9 h60
  text "CERTIFICATION:" at 11293.46,2663.77 h60
  text "MATERIALS AND WORKMANSHIP FOR ALL PCBS" at 12018.46,2663.77 h60
  text "TO MEET OR EXCEED THE REQUIREMENTS OF:" at 12018.46,2569.71 h60
  text "X" at 11655.97,2441.08 h60
  text "ANSI IPC-A-600F CLASS ->" at 11783.96,2441.08 h60
  text "X" at 13431.97,2441.08 h60
  text "2" at 13541.96,2441.08 h60
  text "1" at 13226.96,2439.58 h60
  text "3" at 13895.96,2439.58 h60
  text "X" at 12467.97,2293.39 h60
  text "RoHS" at 12595.96,2293.39 h60
  text "OTHER" at 13240.36,2293.39 h60
  text "PER ORDER" at 13637.42,2293.39 h60
  text "ALL BOARDS MUST MEET OR EXCEED UL94-V0 REQUIREMENTS." at 11321,2139.57 h60
  text "PCB MUST BEAR THE UL94V-0 UL REGISTERED MATERIAL ID NUMBER" at 11321,2023.5 h60
  text "ADDITIONAL REQUIREMENTS:" at 11293.46,1854.08 h60
  text "MICROSECTION:" at 11368.23,1746.95 h60
  text "YES" at 12273.96,1746.95 h60
  text "REQUIRED" at 13135.46,1602.62 h60
  text "BARE BOARD ELEC. TEST:" at 11368.23,1599.76 h60
  text "NONE" at 12673.96,1599.76 h60
  text "X" at 13017.46,1599.76 h60
  text "PER ORDER" at 13727.46,1599.76 h60
  text "XX MIL VIAS REQUIRE NON-CONDUCTIVE FILL AND PLANARIZE" at 11536.38,1394.82 h59
  text "XX MIL VIAS REQUIRE CONDUCTIVE FILL AND PLANARIZE" at 11544.38,1290.84 h60
  text "OUTER XX MIL TRACES REQUIRE 50 OHM SINGLE-ENDED IMPEDANCE" at 11543.39,1127.46 h58
  text "LAYER 2 & 3 (INNER LAYERS) XX MIL WIDE, XX MIL SPACE / TRACES REQUIRE 100 OHM DIFFERENTIAL IMPEDANCE" at 11535.39,891.75 h60
  text ".Layer_Name" at 537,-858.49 h60
M11 Gerber Information:
  lines w10: -332,-930.17 6268,-930.17 ; -332,-726.83 6270,-726.83 ; -332,-523.5 -332,-1133.5 3673,-1133.5 6270,-1133.5 6270,-523.5 -331.5,-523.5 -331.5,-1133.5 1244,-1133.5 ; 2133,-1133.5 2133,-523.5 ; 3400,-726.83 3400,-523.5 ; 4240,-726.83 4240,-523.5 ; 4862,-1140 4862,-937.17
  text "ALL ARTWORK VIEWED FROM TOP SIDE" at -268.5,-655.67 h60
  text "BOARD #:" at 2208,-655.67 h60
  text ".PRJ_Number" at 2753.5,-655.67 h60
  text "REV:" at 3598,-655.67 h60
  text ".PCB_Rev" at 3889.5,-655.67 h60
  text "SVN REV:" at 4436,-655.67 h60
  text ".VersionControl_RevNumber" at 4942,-655.67 h60
  text "LAYER NAME =" at -268.5,-858.49 h60
  text "TID #:" at 2208,-859 h60
  text ".TID" at 2753.5,-859 h60
  text "PLOT NAME =" at -268.5,-1064.34 h60
  text ".plot_File_Name" at 537,-1064.34 h60
  text "GENERATED    :" at 2210,-1064.34 h60
  text ".Print_Date" at 3079.5,-1064.34 h60
  text ".Print_Time" at 3808.5,-1064.34 h60
  text "TEXAS INSTRUMENTS" at 5073,-1064.34 h60
M12 Stackup:
  drawing of 399 lines, arcs and shapes, not listed
  text "Layer" at 5435.63,1915.01 h60
  text "Name" at 5845.55,1915.01 h60
  text "Material" at 6775.29,1915.01 h60
  text "Thickness" at 7635.06,1915.01 h60
  text "Constant" at 8284.89,1915.01 h60
  text "Board Layer Stack" at 8854.75,1915.01 h60
  text "Top Overlay" at 5845.55,1795.01 h60
  text "Top Solder" at 5845.55,1675.01 h60
  text "Solder Resist" at 6775.29,1675.01 h60
  text "0.70mil" at 7635.06,1675.01 h60
  text "3.5" at 8284.89,1675.01 h60
  text "1" at 5435.63,1555.01 h60
  text "Top Layer" at 5845.55,1555.01 h60
  text "1.40mil" at 7635.06,1555.01 h60
  text "Dielectric 1" at 5845.55,1435.01 h60
  text "FR-4 High Tg" at 6775.29,1435.01 h60
  text "8.00mil" at 7635.06,1435.01 h60
  text "4.1" at 8284.89,1435.01 h60
  text "2" at 5435.63,1315.01 h60
  text "GND 1" at 5845.55,1315.01 h60
  text "1.40mil" at 7635.06,1315.01 h60
  text "Dielectric 3" at 5845.55,1195.01 h60
  text "FR-4 High Tg" at 6775.29,1195.01 h60
  text "8.00mil" at 7635.06,1195.01 h60
  text "4.1" at 8284.89,1195.01 h60
  text "3" at 5435.63,1075.01 h60
  text "Signal" at 5845.55,1075.01 h60
  text "1.40mil" at 7635.06,1075.01 h60
  text "Dielectric1" at 5845.55,955.01 h60
  text "FR-4 High Tg" at 6775.29,955.01 h60
  text "20.00mil" at 7635.06,955.01 h60
  text "4.1" at 8284.89,955.01 h60
  text "4" at 5435.63,835.01 h60
  text "GND 2" at 5845.55,835.01 h60
  text "1.40mil" at 7635.06,835.01 h60
  text "Dielectric 4" at 5845.55,715.01 h60
  text "FR-4 High Tg" at 6775.29,715.01 h60
  text "8.00mil" at 7635.06,715.01 h60
  text "4.1" at 8284.89,715.01 h60
  text "5" at 5435.63,595.01 h60
  text "PWR" at 5845.55,595.01 h60
  text "1.40mil" at 7635.06,595.01 h60
  text "Dielectric 2" at 5845.55,475.01 h60
  text "FR-4 High Tg" at 6775.29,475.01 h60
  text "8.00mil" at 7635.06,475.01 h60
  text "4.1" at 8284.89,475.01 h60
  text "6" at 5435.63,355.01 h60
  text "Bottom Layer" at 5845.55,355.01 h60
  text "1.40mil" at 7635.06,355.01 h60
  text "Bottom Solder" at 5845.55,235.01 h60
  text "Solder Resist" at 6775.29,235.01 h60
  text "0.70mil" at 7635.06,235.01 h60
  text "3.5" at 8284.89,235.01 h60
  text "Bottom Overlay" at 5845.55,115.01 h60
  text ".Layer_Name" at 537,-858.49 h60
M13 Component Bodies Top:
  text ".Layer_Name" at 537,-858.49 h60
M14 Component Bodies Bottom:
  text ".Layer_Name" at 537,-858.49 h60
M15 Courtyards Top:
  text ".Layer_Name" at 537,-858.49 h60
M16 Courtyards Bottom:
  text ".Layer_Name" at 537,-858.49 h60
Drill Drawing:
  circle w10: c5449.85,2554.67 r16.58
  circle w10: c5449.85,2554.67 r27.63
  circle w10: c5449.85,2306.03 r27.63
  lines w10: 5422.23,2402.72 5422.23,2416.53 5436.04,2430.35 5422.23,2444.16 5422.23,2457.97 5436.04,2457.97 5449.85,2444.16 5463.67,2457.97 5477.48,2457.97 5477.48,2444.16 5463.67,2430.35 5477.48,2416.53 5477.48,2402.72 5463.67,2402.72 5449.85,2416.53 5436.04,2402.72 5422.23,2402.72 ; 5422.23,2651.36 5449.85,2665.17 5477.48,2651.36 5463.67,2678.99 5477.48,2706.61 5449.85,2692.8 5422.23,2706.61 5436.04,2678.99 5422.23,2651.36 ; 5422.23,2775.68 5477.48,2775.68 5477.48,2830.93 5422.23,2830.93 5422.23,2775.68 ; 5422.23,2913.81 5436.04,2913.81 5449.85,2900 5463.67,2913.81 5477.48,2913.81 5463.67,2927.63 5477.48,2941.44 5463.67,2941.44 5449.85,2955.25 5436.04,2941.44 5422.23,2941.44 5436.04,2927.63 5422.23,2913.81 ; 5422.23,3024.32 5477.48,3024.32 5477.48,3079.57 5422.23,3079.57 5422.23,3024.32 ; 5422.23,3162.45 5436.04,3162.45 5449.85,3148.64 5463.67,3162.45 5477.48,3162.45 5463.67,3176.27 5477.48,3190.08 5463.67,3190.08 5449.85,3203.89 5436.04,3190.08 5422.23,3190.08 5436.04,3176.27 5422.23,3162.45 ; 5422.23,3328.21 5477.48,3328.21 5449.85,3272.96 5422.23,3328.21 ; 5422.23,3411.09 5436.04,3411.09 5436.04,3397.28 5463.67,3397.28 5463.67,3411.09 5477.48,3411.09 5477.48,3438.72 5463.67,3438.72 5463.67,3452.53 5436.04,3452.53 5436.04,3438.72 5422.23,3438.72 5422.23,3411.09 ; 5422.23,3549.23 5449.85,3521.6 5477.48,3549.23 5449.85,3576.85 5422.23,3549.23 ; 5422.23,3659.73 5436.04,3659.73 5436.04,3645.92 5463.67,3645.92 5463.67,3659.73 5477.48,3659.73 5477.48,3687.36 5463.67,3687.36 5463.67,3701.17 5436.04,3701.17 5436.04,3687.36 5422.23,3687.36 5422.23,3659.73 ; 5422.23,3825.49 5477.48,3825.49 5449.85,3770.24 5422.23,3825.49 ; 5433.28,3035.37 5466.43,3035.37 5466.43,3068.52 5433.28,3068.52 5433.28,3035.37 ; 5433.28,3167.98 5441.57,3167.98 5449.85,3159.69 5458.14,3167.98 5466.43,3167.98 5458.14,3176.27 5466.43,3184.55 5458.14,3184.55 5449.85,3192.84 5441.57,3184.55 5433.28,3184.55 5441.57,3176.27 5433.28,3167.98 ; 5433.28,3317.16 5466.43,3317.16 5449.85,3284.01 5433.28,3317.16 ; 5433.28,3416.62 5441.57,3416.62 5441.57,3408.33 5458.14,3408.33 5458.14,3416.62 5466.43,3416.62 5466.43,3433.19 5458.14,3433.19 5458.14,3441.48 5441.57,3441.48 5441.57,3433.19 5433.28,3433.19 5433.28,3416.62
  lines w12: 5372.14,2241.1 8603.63,2241.1 ; 5372.14,3857.26 8603.63,3857.26 ; 5710,2116.78 5710,3981.58 ; 6042,2116.78 6042,3981.58 ; 6678.56,2116.78 6678.56,3981.58 ; 6937.7,2116.78 6937.7,3981.58 ; 7312.86,2116.78 7312.86,3981.58 ; 8037.19,2116.78 8037.19,3981.58 ; 5372.14,2116.78 8603.63,2116.78 8603.63,3981.58 5372.14,3981.58 5372.14,2116.78
  text "Symbol" at 5446.73,3894.56 h72
  text "Quantity" at 5747.3,3894.56 h72
  text "Finished Hole Size" at 6079.3,3894.56 h72
  text "Plated" at 6715.86,3894.56 h72
  text "Hole Type" at 6975,3894.56 h72
  text "Drill Layer Pair" at 7350.16,3894.56 h72
  text "Hole Tolerance" at 8074.49,3894.56 h72
  text "2" at 5747.3,3770.24 h60
  text "39.37mil (1.000mm)" at 6079.3,3770.24 h60
  text "NPTH" at 6715.86,3770.24 h60
  text "Round" at 6975,3770.24 h60
  text "Top Layer - Bottom Layer" at 7350.16,3770.24 h60
  text "4" at 5747.3,3645.92 h60
  text "43.31mil (1.100mm)" at 6079.3,3645.92 h60
  text "NPTH" at 6715.86,3645.92 h60
  text "Round" at 6975,3645.92 h60
  text "Top Layer - Bottom Layer" at 7350.16,3645.92 h60
  text "2" at 5747.3,3521.6 h60
  text "63.00mil (1.600mm)" at 6079.3,3521.6 h60
  text "NPTH" at 6715.86,3521.6 h60
  text "Round" at 6975,3521.6 h60
  text "Top Layer - Bottom Layer" at 7350.16,3521.6 h60
  text "2" at 5747.3,3397.28 h60
  text "129.92mil (3.300mm)" at 6079.3,3397.28 h60
  text "NPTH" at 6715.86,3397.28 h60
  text "Round" at 6975,3397.28 h60
  text "Top Layer - Bottom Layer" at 7350.16,3397.28 h60
  text "24" at 5747.3,3272.96 h60
  text "7.87mil (0.200mm)" at 6079.3,3272.96 h60
  text "PTH" at 6715.86,3272.96 h60
  text "Round" at 6975,3272.96 h60
  text "Top Layer - Bottom Layer" at 7350.16,3272.96 h60
  text "127" at 5747.3,3148.64 h60
  text "10.00mil (0.254mm)" at 6079.3,3148.64 h60
  text "PTH" at 6715.86,3148.64 h60
  text "Round" at 6975,3148.64 h60
  text "Top Layer - Bottom Layer" at 7350.16,3148.64 h60
  text "4" at 5747.3,3024.32 h60
  text "31.50mil (0.800mm)" at 6079.3,3024.32 h60
  text "PTH" at 6715.86,3024.32 h60
  text "Round" at 6975,3024.32 h60
  text "Top Layer - Bottom Layer" at 7350.16,3024.32 h60
  text "6" at 5747.3,2900 h60
  text "35.43mil (0.900mm)" at 6079.3,2900 h60
  text "PTH" at 6715.86,2900 h60
  text "Round" at 6975,2900 h60
  text "Top Layer - Bottom Layer" at 7350.16,2900 h60
  text "47" at 5747.3,2775.68 h60
  text "40.00mil (1.016mm)" at 6079.3,2775.68 h60
  text "PTH" at 6715.86,2775.68 h60
  text "Round" at 6975,2775.68 h60
  text "Top Layer - Bottom Layer" at 7350.16,2775.68 h60
  text "4" at 5747.3,2651.36 h60
  text "43.31mil (1.100mm)" at 6079.3,2651.36 h60
  text "PTH" at 6715.86,2651.36 h60
  text "Round" at 6975,2651.36 h60
  text "Top Layer - Bottom Layer" at 7350.16,2651.36 h60
  text "4" at 5747.3,2527.04 h60
  text "47.24mil (1.200mm)" at 6079.3,2527.04 h60
  text "PTH" at 6715.86,2527.04 h60
  text "Round" at 6975,2527.04 h60
  text "Top Layer - Bottom Layer" at 7350.16,2527.04 h60
  text "2" at 5747.3,2402.72 h60
  text "51.18mil (1.300mm)" at 6079.3,2402.72 h60
  text "PTH" at 6715.86,2402.72 h60
  text "Round" at 6975,2402.72 h60
  text "Top Layer - Bottom Layer" at 7350.16,2402.72 h60
  text "4" at 5747.3,2278.4 h60
  text "125.98mil (3.200mm)" at 6079.3,2278.4 h60
  text "PTH" at 6715.86,2278.4 h60
  text "Round" at 6975,2278.4 h60
  text "Top Layer - Bottom Layer" at 7350.16,2278.4 h60
  text "232 Total" at 5747.3,2154.08 h60
  text ".Layer_Name" at 537,-858.49 h60
M17 Embedded Cavity:
  text ".Layer_Name" at 537,-858.49 h60
M18 Embedded Assembly:
  text ".Layer_Name" at 537,-858.49 h60
M19 Embedded Keepout:
  text ".Layer_Name" at 537,-858.49 h60

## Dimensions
-40,-400 to 960,-400 on M2 Board Dimensions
